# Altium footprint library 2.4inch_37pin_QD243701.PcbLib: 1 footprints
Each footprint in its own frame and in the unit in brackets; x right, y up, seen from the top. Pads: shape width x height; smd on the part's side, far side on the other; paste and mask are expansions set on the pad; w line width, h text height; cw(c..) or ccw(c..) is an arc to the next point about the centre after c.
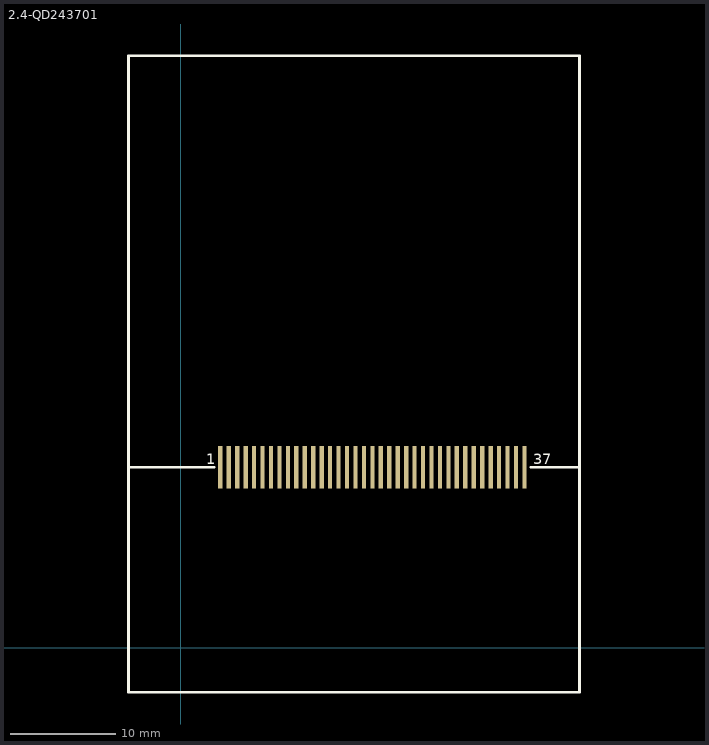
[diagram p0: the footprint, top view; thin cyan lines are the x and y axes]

## 2.4-QD243701 [mm] "2.4 TFT"
pads (37):
  rect 0.4x4 smd: 1(3.747,17.109) 2(4.547,17.109) 3(5.347,17.109) 4(6.147,17.109) 5(6.947,17.109) 6(7.747,17.109) 7(8.547,17.109) 8(9.347,17.109) 9(10.147,17.109) 10(10.947,17.109) 11(11.747,17.109) 12(12.547,17.109) 13(13.347,17.109) 14(14.147,17.109) 15(14.947,17.109) 16(15.747,17.109) 17(16.547,17.109) 18(17.347,17.109) 19(18.147,17.109) 20(18.947,17.109) 21(19.747,17.109) 22(20.547,17.109) 23(21.347,17.109) 24(22.147,17.109) 25(22.947,17.109) 26(23.747,17.109) 27(24.547,17.109) 28(25.347,17.109) 29(26.147,17.109) 30(26.947,17.109) 31(27.747,17.109) 32(28.547,17.109) 33(29.347,17.109) 34(30.147,17.109) 35(30.947,17.109) 36(31.747,17.109) 37(32.547,17.109)
Top Overlay:
  lines w0.254: -4.953,17.109 3.175,17.109 ; 33.147,17.109 37.767,17.109 ; -4.953,-4.191 37.767,-4.191 37.767,56.069 -4.953,56.069 -4.953,-4.191
  text "37" at 33.401,17.399 h1.02
  text "1" at 2.413,17.399 h1.02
